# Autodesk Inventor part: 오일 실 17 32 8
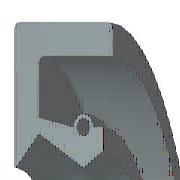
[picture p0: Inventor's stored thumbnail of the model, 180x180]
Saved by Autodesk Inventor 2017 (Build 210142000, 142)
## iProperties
IsCustomPart: 0
Created: 2018-09
Part Number: 오일 실 17 32 8
Material: 고무
Description: 오일-실
Document SubType Name: Modeling
Standard: KS B 2804
Standards Organization: KS
Language: ko-KR
Size Designation: D - 17 32 8
Categories: <MemberInstance><Categories><Category DisplayName="샤프트 부품" InternalName="7f7aeb1f-a693-4053-b835-cee3144e0d98" Mnemonic="SHFT"><Category DisplayName="실링" Intern
Density: 0.93 g/cm^3
Appearance: 고무 - 검은색 - 버전 1.1
Mass: 2.28027 g
Surface Area: 32.1224 cm^2
Volume: 2.45191 cm^3
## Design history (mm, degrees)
revolve "본체" stored, may be unused: angle "d17" = 90 deg
revolve "스프링1" stored, may be unused: angle "d18" = 90 deg
body "Solid1"
sketch "스케치1"
  geometry: L1 (0, 16)-(8, 16); L2 (8, 14.25)-(1.75, 14.25); L3 (1.75, 10.25)-(4.9, 8.5); L4 (4.9, 8.5)-(0, 8.5); L5 (0, 0)-(9.586, 0) reference; L6 (4.9, 8.5)-(6.3, 9.375); L7 (0, 18)-(0, -3) reference; L8 (-1.941, 0)-(11.507, 0) reference; L9 (4.2, 10.6)-(1.75, 11.21); L10 (1.75, 11.21)-(1.75, 14.25); L11 (0, 16)-(0, 8.588); L12 (4.9, 8.5)-(0, 8.5); L13 (1.75, 10.25)-(0.152, 8.528); L14 (8, 16)-(8, 14.25); L15 (5.6, 10.6)-(6.3, 10.6); L16 (6.3, 10.6)-(6.3, 9.375); C1 r 0.455 at (4.9, 10.6); A1 r 0.7 centre (4.9, 10.6) between (5.6, 10.6) and (4.2, 10.6); A2 r 0.088 centre (0.088, 8.588) between (0, 8.588) and (0.152, 8.528); 1 further point
  constraints: 28 end point, 5 horizontal alignment, 5 point on line, 4 point on circle, 4 vertical alignment, 3 centre point, 3 tangent, 2 collinear, 2 horizontal, 2 perpendicular, 1 coincident, 1 parallel
  dimensions: "d0" = 32 diameter of L1 L5 (= SD2); "d1" = 1.75 distance of L1.end L2.start (= SD); "d2" = 0.91 diameter of C1 (= SPDI); "d3" = 1.4 diameter of A1 (= SPDA); "d4" = 17 diameter of L3.end L5 (= NND); "d5" = 20.5 diameter of L3.start L5 (= TKDM); "d7" = 22.42 diameter of L9.end L5 (= TKDM + 0.24 x SWDT); "d8" = 1.75 distance between parallel lines of L11 L10 (= SD); "d9" = 4.9 distance from line of L11 C1.centre (= SPDST); "d10" = 21.2 diameter of C1.centre L5 (= HLDM); "d11" = 0.0875 radius of A2 (= 0.25 x LAB); "d12" = 6.3 distance between parallel lines of L11 L16 (= SDI); "d13" = 18.75 diameter of L6.end L5 (= ABDM); "d14" = 8 distance from line of L11 L1.end (= SWDT)
fillet "모깎기1" dims "d6" = 0.3 (= RR)
other parameters: "SD2" = 32 [user parameter; used in 1 equation term], "SWDT" = 8 [user parameter; used in 2 equation terms], "RR" = 0.3 [user parameter; used in 1 equation term], "SD" = 1.75 [user parameter; used in 2 equation terms], "NND" = 17 [user parameter; used in 1 equation term], "SPDA" = 1.4 [user parameter; used in 1 equation term], "SPDI" = 0.91 [user parameter; used in 1 equation term], "TKDM" = 20.5 [user parameter; used in 2 equation terms], "HLDM" = 21.2 [user parameter; used in 1 equation term], "ABDM" = 18.75 [user parameter; used in 1 equation term], "SDI" = 6.3 [user parameter; used in 1 equation term], "SPDST" = 4.9 [user parameter; used in 1 equation term], "LAB" = 0.35 [user parameter; used in 1 equation term], "d15" = 0, "d16" = 0, "d19" = 0
